(* Logix 5000 project; controller LinePLC1 vendor 1 type 14 code 154 rev 32.11; software revision 32.02 *)

TASK MainTask (continuous, watchdog 500 ms) : MainProgram

MODULES
   Local : vendor 1 type 14 code 154 (PointIO 0, rev 32.11)
      ISC_CAM_145 : ETHERNET-MODULE (Ethernet 192.168.1.145, rev 1.1, Output RPI 10 ms)   // isc-camxb145150d
           ISC_CAM_145:I.Data[0].1   // SystemReady
           ISC_CAM_145:I.Data[1].13   // Power supply voltage low/high
           ISC_CAM_145:I.Data[12].9   // Parameter write OK
           ISC_CAM_145:I.Data[1].10   // Air pressure fault
           ISC_CAM_145:I.Data[1].3   // Product buffer too full
           ISC_CAM_145:I.Data[5]   // Throughput - number of product inducted per minute
           ISC_CAM_145:I.Data[1].15   // Output overcurrent
           ISC_CAM_145:I.Data[3]   // ProductsOnBelt - Count of current products on the belt (Optional in V1 scope)
           ISC_CAM_145:I.Data[0].2   // Belt Moving
           ISC_CAM_145:I.Data[1].4   // AIM peg sensor fault
           ISC_CAM_145:I.Data[2].5   // Product destination signal received late
           ISC_CAM_145:I.Data[2].10   // Belt elongation limit reached
           ISC_CAM_145:I.Data[2].6   // Product did not sort
           ISC_CAM_145:I.Data[4]   // Split Word - 0-7 Products on Belt Byte, 8-15 Belt Speed Byte
           ISC_CAM_145:I.Data[2].14   // High CPU usage
           ISC_CAM_145:I.Data[0].4   // System Warning
           ISC_CAM_145:I.Data[0].5   // System Ready for Next Product
           ISC_CAM_145:I.Data[0].6   // File reading busy
           ISC_CAM_145:I.Data[12].0   // Parameter group
           ISC_CAM_145:I.Data[12].1   // Parameter group
           ISC_CAM_145:I.Data[0].8   // Spare Byte
           ISC_CAM_145:I.Data[1].5   // Product destination signal received too late
           ISC_CAM_145:I.Data[0].9   // Spare Byte
           ISC_CAM_145:I.Data[4].0   // Products of belt
           ISC_CAM_145:I.Data[4].1   // Products of belt
           ISC_CAM_145:I.Data[4].2   // Products of belt
           ISC_CAM_145:I.Data[3].8   // Spare Byte
           ISC_CAM_145:I.Data[12].11   // Parameter value format OK
           ISC_CAM_145:I.Data[12].2   // Parameter group
           ISC_CAM_145:I.Data[1].2   // Outfeed PE jam
           ISC_CAM_145:I.Data[3].0   // IO 0 (C0-Pin4)
           ISC_CAM_145:I.Data[3].9   // Spare Byte
           ISC_CAM_145:I.Data[4].8   // Belt Speed
           ISC_CAM_145:I.Data[4].3   // Products of belt
           ISC_CAM_145:I.Data[4].4   // Products of belt
           ISC_CAM_145:I.Data[4].5   // Products of belt
           ISC_CAM_145:I.Data[0].0   // Life_Bit
           ISC_CAM_145:I.Data[4].9   // Belt Speed
           ISC_CAM_145:I.Data[0]   // Status
           ISC_CAM_145:I.Data[0].10   // Spare Byte
           ISC_CAM_145:I.Data[6].8   // Spare byte
           ISC_CAM_145:I.Data[6].9   // Spare byte
           ISC_CAM_145:I.Data[2].2   // Outfeed PE jam warning
           ISC_CAM_145:I.Data[12].3   // Parameter group
           ISC_CAM_145:I.Data[4].6   // Products of belt
           ISC_CAM_145:I.Data[12].4   // Parameter group
           ISC_CAM_145:I.Data[10]   // Spare Word
           ISC_CAM_145:I.Data[3].1   // IO 1 (C0-Pin2)
           ISC_CAM_145:I.Data[12]   // Parameter group 1 byte - bits 0-7, Paramet feedback 1 byte - 8-15
           ISC_CAM_145:I.Data[1].9   // Motor run signal missing
           ISC_CAM_145:I.Data[12].10   // Parameter type OK
           ISC_CAM_145:I.Data[6].0   // Destination last product
           ISC_CAM_145:I.Data[4].7   // Products of belt
           ISC_CAM_145:I.Data[2].1   // Infeed PE jam warning
           ISC_CAM_145:I.Data[6].1   // Destination last product
           ISC_CAM_145:I.Data[1].0   // Gap between products to small
           ISC_CAM_145:I.Data[6].2   // Destination last product
           ISC_CAM_145:I.Data[0].11   // Spare Byte
           ISC_CAM_145:I.Data[3].2   // IO 2 (C1-Pin4)
           ISC_CAM_145:I.Data[12].8   // Parameter read OK
           ISC_CAM_145:I.Data[2].8   // Belt speed too slow
           ISC_CAM_145:I.Data[12].5   // Parameter group
           ISC_CAM_145:I.Data[12].12   // Spare bit
           ISC_CAM_145:I.Data[12].13   // Spare bit
           ISC_CAM_145:I.Data[12].14   // Spare bit
           ISC_CAM_145:I.Data[12].15   // Spare bit
           ISC_CAM_145:I.Data[1]   // Fault Code Word 1
           ISC_CAM_145:I.Data[1].1   // Infeed PE jam
           ISC_CAM_145:I.Data[1].8   // Encoder fault
           ISC_CAM_145:I.Data[2]   // Fault Code Word 2
           ISC_CAM_145:I.Data[3].10   // Spare Byte
           ISC_CAM_145:I.Data[3].11   // Spare Byte
           ISC_CAM_145:I.Data[3].12   // Spare Byte
           ISC_CAM_145:I.Data[0].12   // Spare Byte
           ISC_CAM_145:I.Data[6].3   // Destination last product
           ISC_CAM_145:I.Data[6].4   // Destination last product
           ISC_CAM_145:I.Data[6].5   // Destination last product
           ISC_CAM_145:I.Data[2].11   // Belt acceleration too fast
           ISC_CAM_145:I.Data[2].12   // Belt deceleration too fast
           ISC_CAM_145:I.Data[11]   // Spare Word
           ISC_CAM_145:I.Data[12].6   // Parameter group
           ISC_CAM_145:I.Data[12].7   // Parameter group
           ISC_CAM_145:I.Data[14]   // Parameter value LSW
           ISC_CAM_145:I.Data[15]   // Parameter value MSW
           ISC_CAM_145:I.Data[3].13   // Spare Byte
           ISC_CAM_145:I.Data[3].14   // Spare Byte
           ISC_CAM_145:I.Data[3].15   // Spare Byte
           ISC_CAM_145:I.Data[4].10   // Belt Speed
           ISC_CAM_145:I.Data[4].11   // Belt Speed
           ISC_CAM_145:I.Data[0].13   // Spare Byte
           ISC_CAM_145:I.Data[0].14   // Spare Byte
           ISC_CAM_145:I.Data[7]   // Spare Word
           ISC_CAM_145:I.Data[8]   // Spare Word
           ISC_CAM_145:I.Data[9]   // Spare Word
           ISC_CAM_145:I.Data[4].12   // Belt Speed
           ISC_CAM_145:I.Data[0].15   // Spare Byte
           ISC_CAM_145:I.Data[2].9   // Belt speed too fast
           ISC_CAM_145:I.Data[3].3   // IO 3 (C1-Pin2)
           ISC_CAM_145:I.Data[13]   // Parameter
           ISC_CAM_145:I.Data[4].13   // Belt Speed
           ISC_CAM_145:I.Data[4].14   // Belt Speed
           ISC_CAM_145:I.Data[0].3   // System Error
           ISC_CAM_145:I.Data[3].4   // IO 4 (C2-Pin4)
           ISC_CAM_145:I.Data[6].6   // Destination last product
           ISC_CAM_145:I.Data[2].3   // Product buffer nearly full
           ISC_CAM_145:I.Data[2].4   // AIM damaged or missing peg
           ISC_CAM_145:I.Data[6]   // Destination last product Byte - bits 0-7
           ISC_CAM_145:I.Data[6].7   // Destination last product
           ISC_CAM_145:I.Data[2].0   // Gap between products to small warning
           ISC_CAM_145:I.Data[3].5   // IO 5 (C2-Pin2)
           ISC_CAM_145:I.Data[4].15   // Belt Speed
           ISC_CAM_145:I.Data[3].6   // IO 6 (C3-Pin4)
           ISC_CAM_145:I.Data[1].12   // IO-Link fault
           ISC_CAM_145:I.Data[3].7   // IO 7 (C3-Pin2)
           ISC_CAM_145:I.Data[6].10   // Spare byte
           ISC_CAM_145:I.Data[6].11   // Spare byte
           ISC_CAM_145:I.Data[6].12   // Spare byte
           ISC_CAM_145:I.Data[6].13   // Spare byte
           ISC_CAM_145:I.Data[6].14   // Spare byte
           ISC_CAM_145:I.Data[6].15   // Spare byte
           ISC_CAM_145:I.Data[0].7   // Spare
           ISC_CAM_145:O.Data[0].0   // Life_Bit
           ISC_CAM_145:O.Data[0].12   // Product from infeed 0
           ISC_CAM_145:O.Data[1].15   // Reserved - set always as 0
           ISC_CAM_145:O.Data[7].2   // Active carryway 1 enable left
           ISC_CAM_145:O.Data[7].3   // Active carryway 1 enable right
           ISC_CAM_145:O.Data[0].13   // Product from infeed 1
           ISC_CAM_145:O.Data[12].9   // Parameter write value
           ISC_CAM_145:O.Data[7].5   // Active carryway 2 enable right
           ISC_CAM_145:O.Data[5]   // Destination 4 1 Byte - bits 0-7, Destination 5 1 Byte - bits 8 15
           ISC_CAM_145:O.Data[12].0   // Parameter group
           ISC_CAM_145:O.Data[12].1   // Parameter group
           ISC_CAM_145:O.Data[12].2   // Parameter group
           ISC_CAM_145:O.Data[0].3   // Reset errors
           ISC_CAM_145:O.Data[12].3   // Parameter group
           ISC_CAM_145:O.Data[1].0   // Product destination
           ISC_CAM_145:O.Data[0].1   // Belt motor running
           ISC_CAM_145:O.Data[13].0   // Read Parameter
           ISC_CAM_145:O.Data[6]   // Destination 6 1 Byte - bits 0-7, Reserved set 0 1 Byte - bits 8 15
           ISC_CAM_145:O.Data[0].4   // Reset warnings
           ISC_CAM_145:O.Data[8].10   // Override active carryway 2
           ISC_CAM_145:O.Data[7].4   // Active carryway 2 enable left
           ISC_CAM_145:O.Data[7].7   // Active carryway 3 enable right
           ISC_CAM_145:O.Data[12].4   // Parameter group
           ISC_CAM_145:O.Data[12].5   // Parameter group
           ISC_CAM_145:O.Data[12].6   // Parameter group
           ISC_CAM_145:O.Data[10]   // Spare word
           ISC_CAM_145:O.Data[1].9   // Run mode PLC
           ISC_CAM_145:O.Data[12].7   // Parameter group
           ISC_CAM_145:O.Data[7].10   // Override active carryway pointer
           ISC_CAM_145:O.Data[13].1   // Whrite Parameter
           ISC_CAM_145:O.Data[6].8   // Reserved - set 0
           ISC_CAM_145:O.Data[6].10   // Reserved - set 0
           ISC_CAM_145:O.Data[6].9   // Reserved - set 0
           ISC_CAM_145:O.Data[11]   // Spare word
           ISC_CAM_145:O.Data[7].6   // Active carryway 3 enable left
           ISC_CAM_145:O.Data[12].10   // Spare bit
           ISC_CAM_145:O.Data[12].11   // Spare bit
           ISC_CAM_145:O.Data[12].12   // Spare bit
           ISC_CAM_145:O.Data[1].8   // Run mode internal
           ISC_CAM_145:O.Data[12].13   // Spare bit
           ISC_CAM_145:O.Data[12].14   // Spare bit
           ISC_CAM_145:O.Data[12].15   // Spare bit
           ISC_CAM_145:O.Data[1].1   // Product destination
           ISC_CAM_145:O.Data[6].11   // Reserved - set 0
           ISC_CAM_145:O.Data[15]   // Spare Word
           ISC_CAM_145:O.Data[7].0   // Reserved
           ISC_CAM_145:O.Data[14]   // Parameter value
           ISC_CAM_145:O.Data[3].0   // Destination 0
           ISC_CAM_145:O.Data[3].1   // Destination 0
           ISC_CAM_145:O.Data[3].2   // Destination 0
           ISC_CAM_145:O.Data[3].3   // Destination 0
           ISC_CAM_145:O.Data[8].1   // Active carryway 1 enable
           ISC_CAM_145:O.Data[3].4   // Destination 0
           ISC_CAM_145:O.Data[3].5   // Destination 0
           ISC_CAM_145:O.Data[3].6   // Destination 0
           ISC_CAM_145:O.Data[8]   // Carryway control
           ISC_CAM_145:O.Data[3].7   // Destination 0
           ISC_CAM_145:O.Data[7].11   // Override active carryway pointer
           ISC_CAM_145:O.Data[0]   // Status
           ISC_CAM_145:O.Data[7].1   // Reserved
           ISC_CAM_145:O.Data[6].12   // Reserved - set 0
           ISC_CAM_145:O.Data[6].13   // Reserved - set 0
           ISC_CAM_145:O.Data[3].8   // Destination 1
           ISC_CAM_145:O.Data[12].8   // Parameter read value
           ISC_CAM_145:O.Data[3].9   // Destination 1
           ISC_CAM_145:O.Data[0].5   // Reset destination counter
           ISC_CAM_145:O.Data[8].2   // Active carryway 2 enable
           ISC_CAM_145:O.Data[8].3   // Active carryway 3 enable
           ISC_CAM_145:O.Data[6].14   // Reserved - set 0
           ISC_CAM_145:O.Data[6].15   // Reserved - set 0
           ISC_CAM_145:O.Data[1]   // Product destination 1 Byte - bits 0-7 - Run modes 1 Byet - bits 8-15
           ISC_CAM_145:O.Data[4].0   // Destination 2
           ISC_CAM_145:O.Data[4].1   // Destination 2
           ISC_CAM_145:O.Data[4].2   // Destination 2
           ISC_CAM_145:O.Data[4].3   // Destination 2
           ISC_CAM_145:O.Data[4].4   // Destination 2
           ISC_CAM_145:O.Data[0].9   // Reserved - set always as 0
           ISC_CAM_145:O.Data[1].2   // Product destination
           ISC_CAM_145:O.Data[1].3   // Product destination
           ISC_CAM_145:O.Data[1].4   // Product destination
           ISC_CAM_145:O.Data[1].5   // Product destination
           ISC_CAM_145:O.Data[1].6   // Product destination
           ISC_CAM_145:O.Data[1].7   // Product destination
           ISC_CAM_145:O.Data[8].11   // Override active carryway 3
           ISC_CAM_145:O.Data[3]   // Destination 0 1 Byte - bits 0-7, Destination 1 1 Byte - bits 8 15
           ISC_CAM_145:O.Data[4]   // Destination 2 1 Byte - bits 0-7, Destination 3 1 Byte - bits 8 15
           ISC_CAM_145:O.Data[4].5   // Destination 2
           ISC_CAM_145:O.Data[4].6   // Destination 2
           ISC_CAM_145:O.Data[4].7   // Destination 2
           ISC_CAM_145:O.Data[4].8   // Destination 3
           ISC_CAM_145:O.Data[4].9   // Destination 3
           ISC_CAM_145:O.Data[5].0   // Destination 4
           ISC_CAM_145:O.Data[3].10   // Destination 1
           ISC_CAM_145:O.Data[3].11   // Destination 1
           ISC_CAM_145:O.Data[3].12   // Destination 1
           ISC_CAM_145:O.Data[5].1   // Destination 4
           ISC_CAM_145:O.Data[5].2   // Destination 4
           ISC_CAM_145:O.Data[5].3   // Destination 4
           ISC_CAM_145:O.Data[5].4   // Destination 4
           ISC_CAM_145:O.Data[5].5   // Destination 4
           ISC_CAM_145:O.Data[5].6   // Destination 4
           ISC_CAM_145:O.Data[5].7   // Destination 4
           ISC_CAM_145:O.Data[5].8   // Destination 5
           ISC_CAM_145:O.Data[5].9   // Destination 5
           ISC_CAM_145:O.Data[6].0   // Destination 6
           ISC_CAM_145:O.Data[3].13   // Destination 1
           ISC_CAM_145:O.Data[3].14   // Destination 1
           ISC_CAM_145:O.Data[3].15   // Destination 1
           ISC_CAM_145:O.Data[4].10   // Destination 3
           ISC_CAM_145:O.Data[4].11   // Destination 3
           ISC_CAM_145:O.Data[4].12   // Destination 3
           ISC_CAM_145:O.Data[6].1   // Destination 6
           ISC_CAM_145:O.Data[6].2   // Destination 6
           ISC_CAM_145:O.Data[6].3   // Destination 6
           ISC_CAM_145:O.Data[6].4   // Destination 6
           ISC_CAM_145:O.Data[6].5   // Destination 6
           ISC_CAM_145:O.Data[6].6   // Destination 6
           ISC_CAM_145:O.Data[6].7   // Destination 6
           ISC_CAM_145:O.Data[4].13   // Destination 3
           ISC_CAM_145:O.Data[4].14   // Destination 3
           ISC_CAM_145:O.Data[4].15   // Destination 3
           ISC_CAM_145:O.Data[5].10   // Destination 5
           ISC_CAM_145:O.Data[5].11   // Destination 5
           ISC_CAM_145:O.Data[5].12   // Destination 5
           ISC_CAM_145:O.Data[7]   // Carryway enable 1 byte - bits 0-7 Override active carryway pointer 1 byte - bits 8-15
           ISC_CAM_145:O.Data[7].8   // Override active carryway pointer
           ISC_CAM_145:O.Data[7].9   // Override active carryway pointer
           ISC_CAM_145:O.Data[7].12   // Override active carryway pointer
           ISC_CAM_145:O.Data[7].13   // Override active carryway pointer
           ISC_CAM_145:O.Data[7].14   // Override active carryway pointer
           ISC_CAM_145:O.Data[7].15   // Override active carryway pointer
           ISC_CAM_145:O.Data[8].9   // Override active carryway 1
           ISC_CAM_145:O.Data[9]   // Override active carryway value
           ISC_CAM_145:O.Data[12]   // Parameter group 1 byte - bits 0-7 Parameter R/W 1 byte - bits 8-15
           ISC_CAM_145:O.Data[2]   // Spare word
           ISC_CAM_145:O.Data[13]   // Parameter
           ISC_CAM_145:O.Data[5].13   // Destination 5
           ISC_CAM_145:O.Data[5].14   // Destination 5
           ISC_CAM_145:O.Data[5].15   // Destination 5
      Discrete_IO : Embedded (PointIO 1, rev 32.11, Output RPI 20 ms)
END_MODULES

ADD_ON_INSTRUCTION ISC_IN   (* revision 1.0 *)
// Input mapping for ISC CAM
VAR_INPUT
   InputWord4 : INT; {required}   // Input Word 4 Data Mapping for Communication
   InputWord6 : INT; {required}   // Input Word 6 Data Mapping for Communication
   InputWord12 : INT; {required}   // Input Word 12 Data Mapping for Communication
        .8   // Parameter Read OK
        .11   // Parameter Value OK
        .10   // Parameter Type OK
        .9   // Parameter Write OK
END_VAR
VAR_OUTPUT
   ProductsOnBelt : INT; {access Read Only, required}   // Number of Products on the Belt
   BeltSpeed : INT; {access Read Only, required}
   LastProductDest : INT; {access Read Only, required}   // Last Product Destination
   ParameterGroup : INT; {access Read Only, required}   // Parameter Group
   ParameterReadOK : BOOL; {access None, required}   // Parameter Read OK
   ParameterTypeOK : BOOL; {access None, required}   // Parameter Type OK
   ParameterValueOK : BOOL; {access None, required}   // Parameter Value Format OK
   ParameterWriteOK : BOOL; {access None, required}   // Parameter Write OK
END_VAR
VAR
   BTDT_IW4B0 : FBD_BIT_FIELD_DISTRIBUTE := (Length := 1); {access None}
   BTDT_IW6B0 : FBD_BIT_FIELD_DISTRIBUTE := (Length := 1); {access None}
   BTDT_IW12B0 : FBD_BIT_FIELD_DISTRIBUTE := (Length := 1); {access None}
   BTDT_IW4B1 : FBD_BIT_FIELD_DISTRIBUTE := (Length := 1); {access None}
END_VAR

ROUTINE Logic   (* structured text *)
   //Input Word 4 Mapping
   BTDT_IW4B0.Source:=InputWord4;
   BTDT_IW4B0.Target:=ProductsOnBelt;
   BTDT(BTDT_IW4B0);
   ProductsOnBelt:=BTDT_IW4B0.Dest;
   
   BTDT_IW4B1.Source:=InputWord4;
   BTDT_IW4B1.Target:=BeltSpeed;
   BTDT(BTDT_IW4B1);
   BeltSpeed:=BTDT_IW4B1.Dest;
   
   //Input Word 6 Mapping
   BTDT_IW6B0.Source:=InputWord6;
   BTDT_IW6B0.Target:=LastProductDest;
   BTDT(BTDT_IW6B0);
   LastProductDest:=BTDT_IW6B0.Dest;
   
   //Input Word 12 Mapping
   BTDT_IW12B0.Source:=InputWord12;
   BTDT_IW12B0.Target:=ParameterGroup;
   BTDT(BTDT_IW12B0);
   ParameterGroup:=BTDT_IW12B0.Dest;
   
   ParameterReadOK:=InputWord12.8;
   ParameterWriteOK:=InputWord12.9;
   ParameterTypeOK:=InputWord12.10;
   ParameterValueOK:=InputWord12.11;
END_ROUTINE
END_ADD_ON_INSTRUCTION

ADD_ON_INSTRUCTION ISC_OUT   (* revision 1.0 *)
// Output mapping for ISC CAM
VAR_OUTPUT
   OutputWord1 : INT; {required}   // Output Word 1 Data Mapping for Communication
        .9   // Run Mode External PLC
        .8   // Run Mode Internal ISC CAM
   OutputWord3 : INT; {access Read Only, required}   // Output Word 3 Data Mapping for Communication
   OutputWord4 : INT; {access Read Only, required}   // Output Word 4 Data Mapping for Communication
   OutputWord5 : INT; {access Read Only, required}   // Output Word 5 Data Mapping for Communication
   OutputWord6 : INT; {required}   // Output Word 6 Data Mapping for Communication
END_VAR
VAR_INPUT
   OutputWord7 : INT; {required}   // Output Word 7 Data Mapping for Communication
        .2   // Active Carryway 1 Enable Left
        .4   // Active Carryway 2 Enable Left
        .6   // Active Carryway 3 Enable Left
        .5   // Active Carryway 2 Enable Right
        .7   // Active Carryway 3 Enable Right
        .3   // Active Carryway 1 Enable Right
END_VAR
VAR_OUTPUT
   OutputWord12 : INT; {access Read Only, required}   // Output Word 12 Data Mapping for Communication
        .9   // Parameter Write Value Trigger
        .8   // Parameter Read Value Trigger
END_VAR
VAR_INPUT
   ProductDest : INT; {required}   // Product Destination
   RunModeInternal : BOOL; {required}   // Run Mode Internal ISC CAM Logic Control
   RunModeExternal : BOOL; {required}   // Run Mode External PLC Logic Control
   ProductsDest0 : INT; {required}   // Number of Products to Destination 0
   ProductsDest1 : INT; {required}   // Number of Products to Destination 1
   ProductsDest2 : INT; {required}   // Number of Products to Destination 2
   ProductsDest3 : INT; {required}   // Number of Products to Destination 3
   ProductsDest4 : INT; {required}   // Number of Products to Destination 4
   ProductsDest5 : INT; {required}   // Number of Products to Destination 5
   ProductsDest6 : INT; {required}   // Number of Products to Destination 6
   EnableLeftCarryway1 : BOOL; {required}   // Active Carryway 1 Enable Left
   EnableRightCarryway1 : BOOL; {required}   // Active Carryway 1 Enable Right
   EnableLeftCarryway2 : BOOL; {required}   // Active Carryway 2 Enable Left
   EnableRightCarryway2 : BOOL; {required}   // Active Carryway 2 Enable Right
   EnableLeftCarryway3 : BOOL; {required}   // Active Carryway 3 Enable Left
   EnableRightCarryway3 : BOOL; {required}   // Active Carryway 3 Enable Right
   OverrideCarrywayPointer : INT; {required}   // Override Active Carryway Pointer
   ParameterGroup : INT; {required}   // Parameter Group
   ParameterRead : BOOL; {required}   // Parameter Read Trigger
   ParameterWrite : BOOL; {required}   // Parameter Write Trigger
END_VAR
VAR
   BTDT_OW1B0 : FBD_BIT_FIELD_DISTRIBUTE := (Length := 1); {access None}
   BTDT_OW3B0 : FBD_BIT_FIELD_DISTRIBUTE := (Length := 1); {access None}
   BTDT_OW4B0 : FBD_BIT_FIELD_DISTRIBUTE := (Length := 1); {access None}
   BTDT_OW5B0 : FBD_BIT_FIELD_DISTRIBUTE := (Length := 1); {access None}
   BTDT_OW6B0 : FBD_BIT_FIELD_DISTRIBUTE := (Length := 1); {access None}
   BTDT_OW7B1 : FBD_BIT_FIELD_DISTRIBUTE := (Length := 1); {access None}
   BTDT_OW12B0 : FBD_BIT_FIELD_DISTRIBUTE := (Length := 1); {access None}
   BTDT_OW3B1 : FBD_BIT_FIELD_DISTRIBUTE := (Length := 1); {access None}
   BTDT_OW4B1 : FBD_BIT_FIELD_DISTRIBUTE := (Length := 1); {access None}
   BTDT_OW5B1 : FBD_BIT_FIELD_DISTRIBUTE := (Length := 1); {access None}
END_VAR

ROUTINE Logic   (* structured text *)
   //Output Word 1 Mapping
   BTDT_OW1B0.Source:=ProductDest;
   BTDT_OW1B0.Target:=OutputWord1;
   BTDT(BTDT_OW1B0);
   OutputWord1:=BTDT_OW1B0.Dest;
   
   OutputWord1.8:=RunModeInternal;
   OutputWord1.9:=RunModeExternal;
   
   //Output Word 3 Mapping
   BTDT_OW3B0.Source:=ProductsDest0;
   BTDT_OW3B0.Target:=OutputWord3;
   BTDT(BTDT_OW3B0);
   OutputWord3:=BTDT_OW3B0.Dest;
   
   BTDT_OW3B1.Source:=ProductsDest1;
   BTDT_OW3B1.Target:=OutputWord3;
   BTDT(BTDT_OW3B1);
   OutputWord3:=BTDT_OW3B1.Dest;
   
   //Output Word 4 Mapping
   BTDT_OW4B0.Source:=ProductsDest2;
   BTDT_OW4B0.Target:=OutputWord4;
   BTDT(BTDT_OW4B0);
   OutputWord4:=BTDT_OW4B0.Dest;
   
   BTDT_OW4B1.Source:=ProductsDest3;
   BTDT_OW4B1.Target:=OutputWord4;
   BTDT(BTDT_OW4B1);
   OutputWord4:=BTDT_OW4B1.Dest;
   
   //Output Word 5 Mapping
   BTDT_OW5B0.Source:=ProductsDest4;
   BTDT_OW5B0.Target:=OutputWord5;
   BTDT(BTDT_OW5B0);
   OutputWord5:=BTDT_OW5B0.Dest;
   
   BTDT_OW5B1.Source:=ProductsDest5;
   BTDT_OW5B1.Target:=OutputWord5;
   BTDT(BTDT_OW5B1);
   OutputWord5:=BTDT_OW5B1.Dest;
   
   //Output Word 6 Mapping
   BTDT_OW6B0.Source:=ProductsDest6;
   BTDT(BTDT_OW6B0);
   OutputWord6:=BTDT_OW6B0.Dest;
   
   //Output Word 7 Mapping
   OutputWord7.2:=EnableLeftCarryway1;
   OutputWord7.3:=EnableRightCarryway1;
   OutputWord7.4:=EnableLeftCarryway2;
   OutputWord7.5:=EnableRightCarryway2;
   OutputWord7.6:=EnableLeftCarryway3;
   OutputWord7.7:=EnableRightCarryway3;
   
   BTDT_OW7B1.Source:=OverrideCarrywayPointer;
   BTDT_OW7B1.Target:=OutputWord7;
   BTDT(BTDT_OW7B1);
   OutputWord7:=BTDT_OW7B1.Dest;
   
   //Output Word 12 Mapping
   BTDT_OW12B0.Source:=ParameterGroup;
   BTDT_OW12B0.Target:=OutputWord12;
   BTDT(BTDT_OW12B0);
   OutputWord12:=BTDT_OW12B0.Dest;
   
   OutputWord12.8:=ParameterRead;
   OutputWord12.9:=ParameterWrite;
END_ROUTINE
END_ADD_ON_INSTRUCTION

PROGRAM MainProgram   (* main routine MainRoutine *)
VAR
   BeltSpeed : INT;
   DestProduct : INT;
   EnableLeftCarryway : SINT;
   EnableRightCarryway : SINT;
   ExternalControl : BOOL;
   ISC_IN : ISC_IN := (InputWord12 := 257, ParameterGroup := 1, ParameterReadOK := 1);
   ISC_OUT : ISC_OUT := (OutputWord1 := 256, OutputWord3 := 8, OutputWord4 := 5, OutputWord5 := 12, OutputWord6 := 2, OutputWord12 := 257, RunModeInternal := 1, ProductsDest0 := 8, ProductsDest2 := 5, ProductsDest4 := 12, ProductsDest6 := 2, ParameterGroup := 1, ParameterRead := 1);
   LastProductDest : INT;
   OverrideCarrywayPointer : INT;
   ParameterGroupRead : INT := 1;
   ParameterGroupWrite : INT := 1;
   ParameterRead : BOOL := 1;
   ParameterReadOK : BOOL := 1;
   ParameterTypeOK : BOOL;
   ParameterValueOK : BOOL;
   ParameterWrite : BOOL;
   ParameterWriteOK : BOOL;
   ProductsOnBelt : INT;
   QuantityLane0 : INT := 8;
   QuantityLane1 : INT;
   QuantityLane2 : INT := 5;
   QuantityLane3 : INT;
   QuantityLane4 : INT := 12;
   QuantityLane5 : INT;
   QuantityLane6 : DINT := 2;
   RunModeExternal : BOOL;   // Run Mode 0 = Internal 1 = External
   RunModeInternal : BOOL := 1;   // Run Mode 1 = Internal 0 = External
   WriteDest : INT;
END_VAR

ROUTINE DS_Testing   (* ladder *)
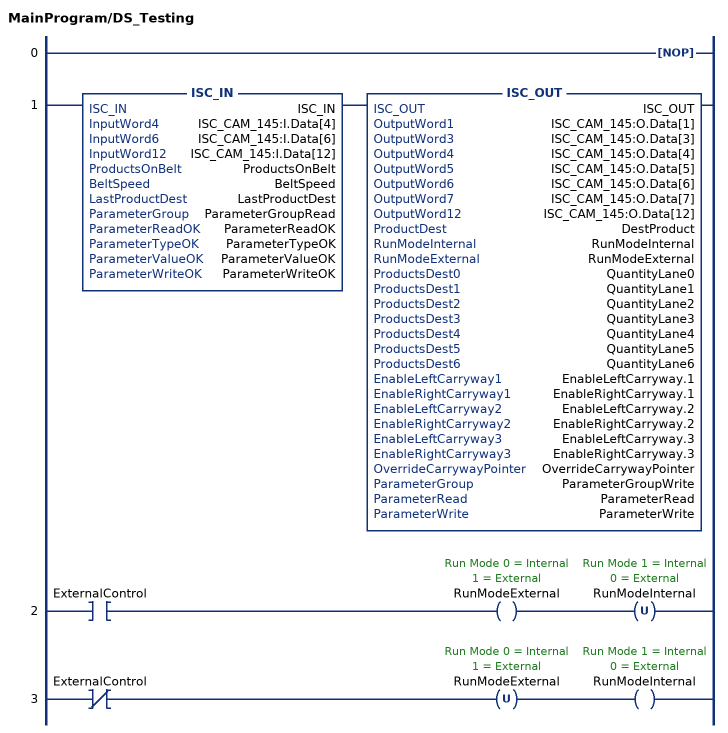
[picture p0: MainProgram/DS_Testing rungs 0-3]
   0: NOP();
   1: ISC_IN(ISC_IN,ISC_CAM_145:I.Data[4],ISC_CAM_145:I.Data[6],ISC_CAM_145:I.Data[12],ProductsOnBelt,BeltSpeed,LastProductDest,ParameterGroupRead,ParameterReadOK,ParameterTypeOK,ParameterValueOK,ParameterWriteOK)ISC_OUT(ISC_OUT,ISC_CAM_145:O.Data[1],ISC_CAM_145:O.Data[3],ISC_CAM_145:O.Data[4],ISC_CAM_145:O.Data[5],ISC_CAM_145:O.Data[6],ISC_CAM_145:O.Data[7],ISC_CAM_145:O.Data[12],DestProduct,RunModeInternal,RunModeExternal,QuantityLane0,QuantityLane1,QuantityLane2,QuantityLane3,QuantityLane4,QuantityLane5,QuantityLane6,EnableLeftCarryway.1,EnableRightCarryway.1,EnableLeftCarryway.2,EnableRightCarryway.2,EnableLeftCarryway.3,EnableRightCarryway.3,OverrideCarrywayPointer,ParameterGroupWrite,ParameterRead,ParameterWrite);
   2: XIC(ExternalControl)OTE(RunModeExternal)OTU(RunModeInternal);
   3: XIO(ExternalControl)OTU(RunModeExternal)OTE(RunModeInternal);
END_ROUTINE

ROUTINE MainRoutine   (* ladder *)
// Main Program Sweep (Cycle)
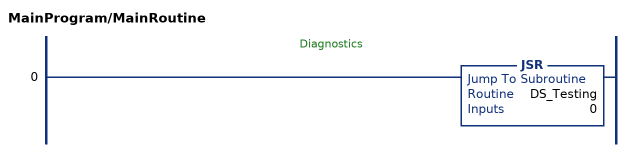
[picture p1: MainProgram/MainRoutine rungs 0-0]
   // Diagnostics
   0: JSR(DS_Testing,0);
END_ROUTINE
END_PROGRAM
